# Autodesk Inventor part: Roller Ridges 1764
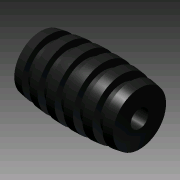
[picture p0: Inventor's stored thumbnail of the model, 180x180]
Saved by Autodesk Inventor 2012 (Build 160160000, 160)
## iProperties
Created: 2007-11
Part Number: Roller Ridges 1764
Document SubType Name: Modeling
Designer: lwoods
Density: 1.4 g/cm^3
Material: PVC-Piping
Mass: 16.1581 g
Surface Area: 36.0602 cm^2
Volume: 11.5415 cm^3
Author: lwoods
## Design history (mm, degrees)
sketch "Sketch1"
  geometry: L1 (-20.301, 0.313)-(-20.301, -6.037); L2 (-20.301, -6.037)-(15.259, -6.037); L3 (15.259, -6.037)-(15.259, 0.313); L4 (-25.63, -9.212)-(23.111, -9.212); L5 (-0.933, 1.965)-(-0.933, -0.385); L6 (-0.933, -0.385)-(-4.108, -0.385); L7 (-4.108, -0.385)-(-4.108, 1.965); L8 (-13.847, 1.306)-(-13.847, -1.476); L9 (-13.847, -1.476)-(-17.022, -1.476); L10 (-17.022, -1.476)-(-17.022, 0.874); L11 (11.98, 0.874)-(11.98, -1.476); L12 (11.98, -1.476)-(8.805, -1.476); L13 (8.805, -1.476)-(8.805, 1.306); L14 (-7.392, 1.854)-(-7.392, -0.71); L15 (-7.392, -0.71)-(-10.567, -0.71); L16 (-10.567, -0.71)-(-10.567, 1.639); L17 (5.526, 1.639)-(5.526, -0.71); L18 (5.526, -0.71)-(2.351, -0.71); L19 (2.351, -0.71)-(2.351, 1.854); A1 r 95.758 centre (-2.521, -93.78) between (-17.022, 0.874) and (-20.301, 0.313); A2 r 95.758 centre (-2.521, -93.78) between (-10.567, 1.639) and (-13.847, 1.306); A3 r 95.758 centre (-2.521, -93.78) between (-4.108, 1.965) and (-7.392, 1.854); A4 r 95.758 centre (-2.521, -93.78) between (2.351, 1.854) and (-0.933, 1.965); A5 r 95.758 centre (-2.521, -93.78) between (15.259, 0.313) and (11.98, 0.874); A6 r 95.758 centre (-2.521, -93.78) between (8.805, 1.306) and (5.526, 1.639)
  constraints: 38 end point, 12 point on circle, 6 centre point, 6 parallel, 2 perpendicular, 1 vertical
  dimensions: "d0" = 35.56 distance of L1.end L2.end; "d1" = 6.35 distance of L1.start L1.end; "d2" = 6.35 distance of L2.end L3.end; "d4" = 3.175 distance between parallel lines of L2 L4; "d7" = 3.175 distance between parallel lines of L5 L7; "d10" = 3.27914 distance between parallel lines of L1 L10; "d11" = 3.175 distance between parallel lines of L14 L16; "d13" = 3.27914 distance between parallel lines of L16 L8; "d16" = 3.27914 distance between parallel lines of L13 L17; "d18" = 3.27914 distance between parallel lines of L3 L11; "d19" = 16.1925 distance between parallel lines of L7 L1; "d20" = 3.175 distance of L17.end L18.end; "d21" = 3.175 distance of L11.end L12.end; "d22" = 3.175 distance of L8.end L9.end; "d23" = 2.3495 distance of L5.start L5.end; "d24" = 2.3495 distance of L17.start L17.end; "d25" = 2.3495 distance of L11.start L11.end; "d26" = 2.3495 distance of L15.end L16.end; "d27" = 2.3495 distance of L9.end L10.end; "d28" = 7.73632 distance between parallel lines of L4 L9; "d29" = 8.50195 distance between parallel lines of L4 L15; "d30" = 8.82748 distance between parallel lines of L4 L6
revolve "Revolution1" sketch "Sketch1" stored, may be unused: angle "d5" = 90 deg
body "Solid1"
other parameters: "d3" = 95.758
